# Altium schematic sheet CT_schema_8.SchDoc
size 308 x 210 mm
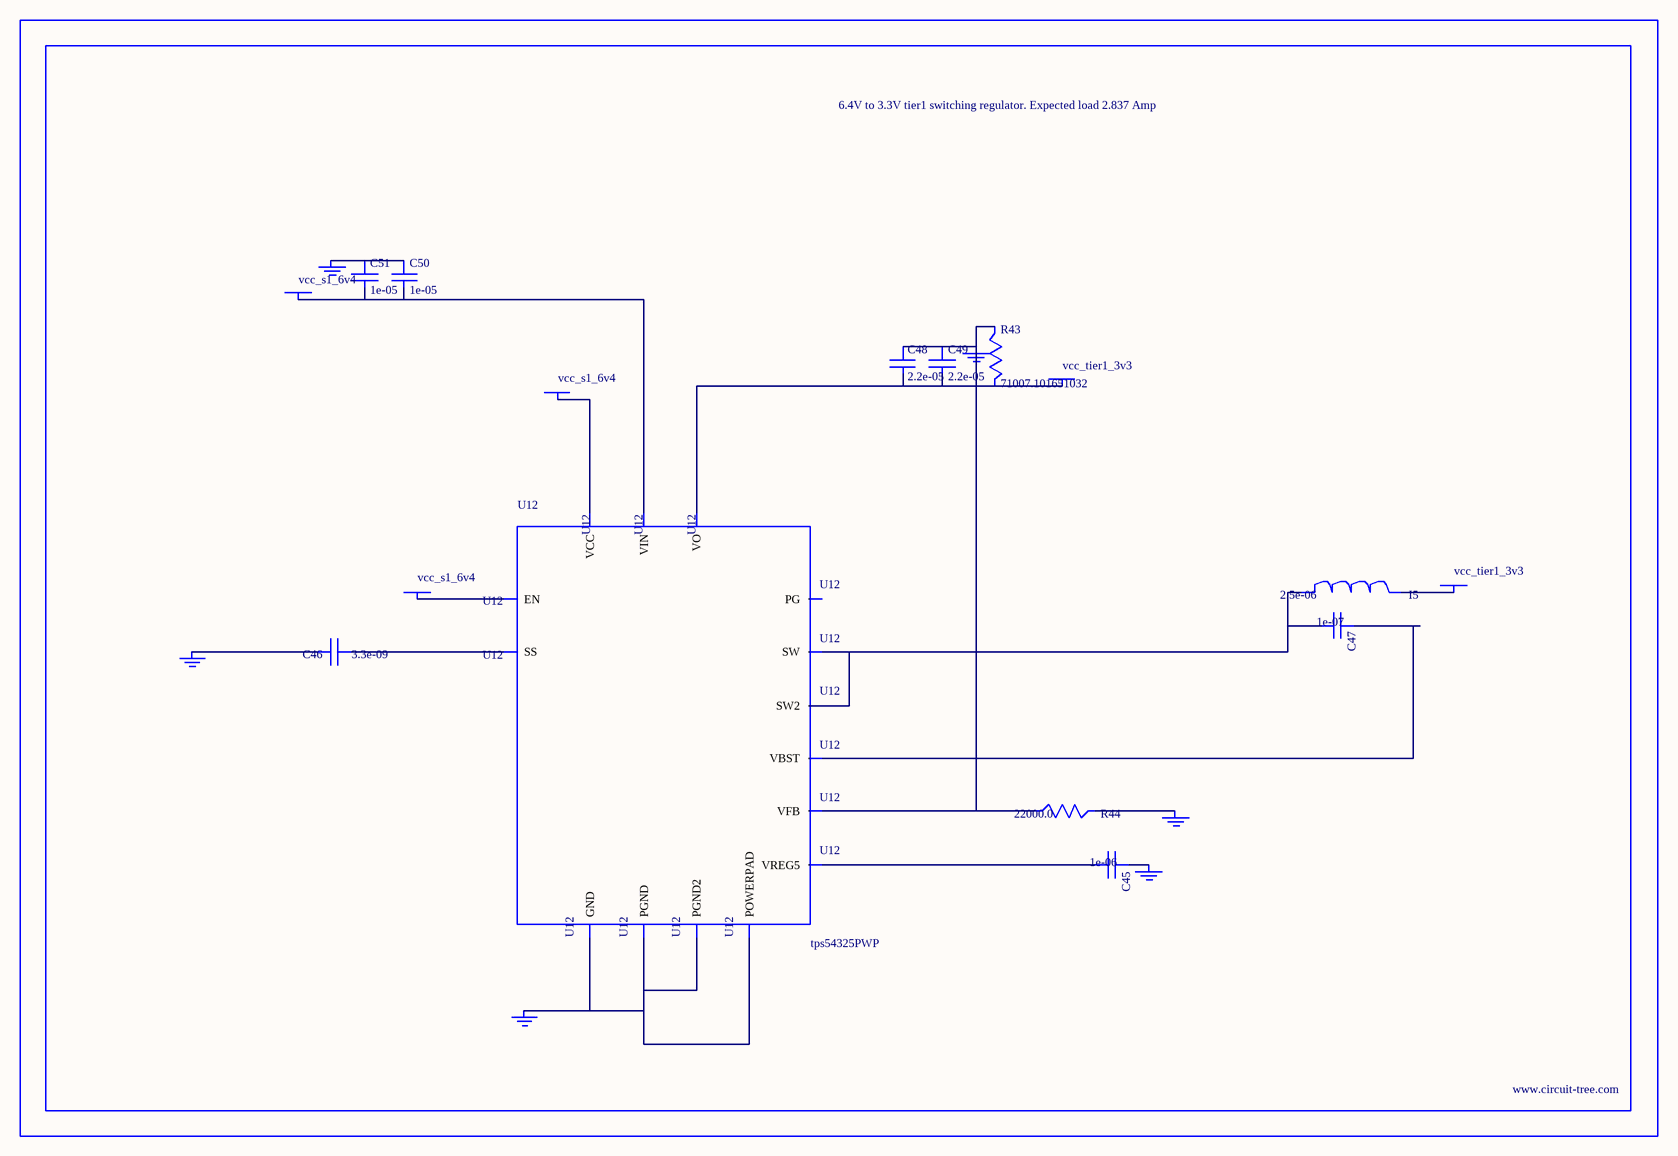
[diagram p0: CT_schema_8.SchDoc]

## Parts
BORDER7  (no value)
C45  1e-06  [C0603]
C46  3.3e-09  [C0402]
C47  1e-07  [C0402]
C48  2.2e-05  [C1210]
C49  2.2e-05  [C1210]
C50  1e-05  [C0805]
C51  1e-05  [C0805]
GND_INSTANCE_7_0  (no value)
GND_INSTANCE_7_1  (no value)
GND_INSTANCE_7_2  (no value)
GND_INSTANCE_7_3  (no value)
GND_INSTANCE_7_4  (no value)
GND_INSTANCE_7_5  (no value)
I5  2.5e-06  [DR1040]
POWER_INSTANCE_7_0  vcc_tier1_3v3
POWER_INSTANCE_7_1  vcc_s1_6v4
POWER_INSTANCE_7_2  vcc_tier1_3v3
POWER_INSTANCE_7_3  vcc_s1_6v4
POWER_INSTANCE_7_4  vcc_s1_6v4
R43  71007.101651032  [R0603]
R44  22000.0  [R0603]
U12  tps54325PWP  [HTSSOP14]

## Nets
NetC45_1: C45.1 GND_INSTANCE_7_2.0(GND)
NetC45_2: C45.2 U12.3(VREG5)
NetC46_1: C46.1 U12.4(SS)
NetC46_2: C46.2 GND_INSTANCE_7_3.0(GND)
NetC47_1: C47.1 U12.12(VBST)
NetC47_2: C47.2 I5.1 U12.10(SW) U12.11(SW2)
NetC48_1: C48.1 C49.1 GND_INSTANCE_7_0.0(GND) R43.1 R44.1 U12.2(VFB)
NetC48_2: C48.2 C49.2 POWER_INSTANCE_7_0.0(PWR) R43.2 U12.1(VO)
NetC50_1: C50.1 C51.1 GND_INSTANCE_7_5.0(GND)
NetC50_2: C50.2 C51.2 POWER_INSTANCE_7_3.0(PWR) U12.13(VIN)
NetGND_INSTANCE_7_1_0: GND_INSTANCE_7_1.0(GND) R44.2
NetGND_INSTANCE_7_4_0: GND_INSTANCE_7_4.0(GND) U12.5(GND) U12.8(PGND) U12.9(PGND2) U12.15(POWERPAD)
NetI5_2: I5.2 POWER_INSTANCE_7_2.0(PWR)
NetPOWER_INSTANCE_7_1_0: POWER_INSTANCE_7_1.0(PWR) U12.7(EN)
NetPOWER_INSTANCE_7_4_0: POWER_INSTANCE_7_4.0(PWR) U12.14(VCC)

Not connected (* = marked no-connect by the designer): U12 6(PG)

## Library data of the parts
BORDER7 = BORDER_PAGE7
C45 = C0603C105K3RACTU
C46 = C0402C332K3RAC
C47 = C0402C104K3RACTU
C48 C49 = GRM32ER61E226ME15L
C50 C51 = C0805C106K8RACTU
GND_INSTANCE_7_0-GND_INSTANCE_7_5 = GND
I5 = DR1040-2R5-R
POWER_INSTANCE_7_0-POWER_INSTANCE_7_4 = PWR
R43 = R43
R44 = RC0603JR-0722KL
